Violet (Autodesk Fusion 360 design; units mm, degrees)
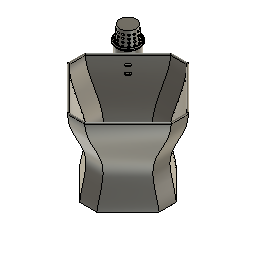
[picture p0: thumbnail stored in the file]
parameter "wall" = 1.35
parameter "height" = 119 (= "Size * 0.7") comment "Vase Hight (Medium setting)"
parameter "tolerance" = 0.15
sketch "Sketch1" plane through (0, 0, 0) normal (0, 0, 1) x axis (1, 0, 0)
  line L1 (-79.0621, -79.0621) -> (79.0621, -79.0621)
  line L2 (-79.0621, 79.0621) -> (-79.0621, -79.0621)
  line L3 (79.0621, 79.0621) -> (-79.0621, 79.0621)
  line L4 (79.0621, -79.0621) -> (79.0621, 79.0621)
  line L5 (-79.0621, 79.0621) -> (79.0621, -79.0621)
  line L6 (79.0621, 79.0621) -> (-79.0621, -79.0621)
  line L7 (-75.5266, 82.5976) -> (82.5976, -75.5266)
  line L8 (-82.5976, 75.5266) -> (75.5266, -82.5976)
  line L9 (-5.9379, 73.9379) -> (62.0621, 5.9379)
  line L10 (-73.9379, 5.9379) -> (-5.9379, 73.9379)
  line L11 (-5.9379, -62.0621) -> (-73.9379, 5.9379)
  line L12 (62.0621, 5.9379) -> (-5.9379, -62.0621)
  line L13 (-73.9379, 5.9379) -> (62.0621, 5.9379)
  line L14 (-5.9379, -62.0621) -> (-5.9379, 73.9379)
  line L15 (-5.9379, 79.0621) -> (-5.9379, 5.9379)
  line L16 (-2.4024, 9.4734) -> (-9.4734, 2.4024)
  line L17 (-60.5266, 67.5976) -> (-67.5976, 60.5266)
  circle C1 centre (-5.9379, 5.9379) radius 85
  circle C2 centre (-64.0621, 64.0621) radius 15
  circle C3 centre (-5.9379, 5.9379) radius 68
  circle C4 centre (-64.0621, 64.0621) radius 13.65
  circle C5 centre (-64.0621, 64.0621) radius 13.5
  circle C6 centre (-5.9379, 5.9379) radius 67.2
  point P6 (0, 0)
  point P1 (0, 0)
  point P7 (-5.9379, 5.9379)
  point P8 (-64.0621, 64.0621)
  point P9 (-5.9379, 5.9379)
  point P19 (-5.9379, 5.9379)
  point P15 (62.0621, 5.9379)
  point P20 (-5.9379, 5.9379)
  point P21 (-5.9379, 79.0621)
  point P22 (-9.4734, 2.4024)
  point P23 (-2.4024, 9.4734)
  point P26 (-5.9379, 5.9379)
  point P27 (-67.5976, 60.5266)
  point P28 (-60.5266, 67.5976)
  point P24 (-64.0621, 64.0621)
  horizontal L1
  perpendicular L1 L2
  parallel L1 L3
  parallel L2 L4
  coincident L5 P6
  coincident L6 P6
  coincident P1 P6
  coincident L5 P7
  coincident L5 P8
  tangent L3 C2
  tangent L4 C1
  coincident P7 P9
  perpendicular L9 L10
  parallel L9 L11
  parallel L10 L12
  coincident L13 P19
  coincident L14 P19
  coincident P9 P19
  equal L9 L12
  coincident C3 P15
  coincident P9 P20
  coincident L3 P21
  perpendicular L3 L15
  coincident L8 P22
  coincident L7 P23
  perpendicular L7 L16
  equal L2 L3
  midpoint P19 L16
  coincident P19 P26
  tangent C2 C6
  coincident L8 P27
  coincident L7 P28
  perpendicular L7 L17
  coincident P24 L17
  dimension "Size" diameter C1 = 170
  dimension "d5" diameter C2 = 30
  dimension "d8" = 5
  dimension "d9" = -5
  dimension "d16" = -17 (= "-Size * 0.1")
  dimension "d17" angle L13 L15 = 90
  dimension "d81" distance P7 P8 = 82.2 (= "Size * 0.42 + ( wall * 8 )")
work_plane "WorkPlane1" AlongDistance 39.6667 (= "height / 3")
work_plane "WorkPlane2" AlongDistance 119 (= "height")
work_plane "WorkPlane5" AlongDistance 71.4 (= "height * 0.6")
work_plane "WorkPlane4" RotateAngle 90
sketch "Sketch2" plane through (0, 0, 39.6667) normal (0, 0, 1) x axis (1, 0, 0)
  line L1 (-5.9379, 90.9379) -> (-5.9379, 5.9379)
  line L2 (-5.9379, 65.4379) -> (53.5621, 5.9379)
  line L3 (-65.4379, 5.9379) -> (-5.9379, 65.4379)
  line L4 (-5.9379, -53.5621) -> (-65.4379, 5.9379)
  line L5 (53.5621, 5.9379) -> (-5.9379, -53.5621)
  line L6 (-65.4379, 5.9379) -> (53.5621, 5.9379)
  line L7 (-5.9379, -53.5621) -> (-5.9379, 65.4379)
  circle C1 centre (-5.9379, 5.9379) radius 85
  circle C2 centre (-5.9379, 5.9379) radius 59.5
  point P2 (-5.9379, 5.9379)
  point P4 (-5.9379, 5.9379)
  point P5 (-5.9379, 90.9379)
  point P10 (-5.9379, 5.9379)
  point P6 (53.5621, 5.9379)
  coincident P2 P4
  coincident C1 P5
  vertical L1
  perpendicular L2 L3
  parallel L2 L4
  parallel L3 L5
  coincident L6 P10
  coincident L7 P10
  coincident P2 P10
  equal L2 L5
  coincident C2 P6
  dimension "d14" = -25.5 (= "-Size * 0.15")
  dimension "d15" angle L1 L6 = 90
sketch "Sketch3" plane through (0, 0, 119) normal (0, 0, 1) x axis (1, 0, 0)
  line L1 (-5.9379, 90.9379) -> (79.0621, 5.9379)
  line L2 (-90.9379, 5.9379) -> (-5.9379, 90.9379)
  line L3 (-5.9379, -79.0621) -> (-90.9379, 5.9379)
  line L4 (79.0621, 5.9379) -> (-5.9379, -79.0621)
  line L5 (-90.9379, 5.9379) -> (79.0621, 5.9379)
  line L6 (-5.9379, -79.0621) -> (-5.9379, 90.9379)
  line L7 (-5.9379, 90.9379) -> (-5.9379, 5.9379)
  circle C1 centre (-5.9379, 5.9379) radius 85
  circle C2 centre (-64.0621, 64.0621) radius 15
  circle C3 centre (-64.0621, 64.0621) radius 7.5
  point P7 (-5.9379, 5.9379)
  point P2 (-5.9379, 5.9379)
  point P3 (79.0621, 5.9379)
  point P8 (-5.9379, 5.9379)
  point P9 (-5.9379, 90.9379)
  perpendicular L1 L2
  parallel L1 L3
  parallel L2 L4
  coincident L5 P7
  coincident L6 P7
  coincident P2 P7
  equal L1 L4
  coincident C1 P3
  coincident P2 P8
  coincident C1 P9
  vertical L7
  concentric C2 C3
  dimension "d18" angle L5 L7 = 90
  dimension "d126" diameter C3 = 15
sketch "Sketch9" plane through (0, 0, 71.4) normal (0, 0, 1) x axis (1, 0, 0)
  circle C1 centre (-64.0621, 64.0621) radius 13.65
  circle C2 centre (-64.0621, 64.0621) radius 11
  concentric C1 C2
  dimension "d127" diameter C2 = 22
loft "Loft2" sketch "Sketch1" + "Sketch9" + "Sketch3" Start Weight 4.0298 Start TakeOff Angle 0 End Weight -3.9427 End TakeOff Angle 0
loft "Loft1" sketch "Sketch1" + "Sketch2" + "Sketch3" Start Weight 1.991 Start TakeOff Angle 0 End Weight -1.8239 End TakeOff Angle 0
chamfer "Chamfer4" distance 17 (= "Size * 0.1")
extrude "Extrude2" new body sketch "Sketch1" profile of C1 C2 L7 L8 C3 L9 L10 L16 C4 C5 C6 L17 blind 15 from offset 3
extrude "Extrude3" sketch "Sketch1" profile of C1 C2 L7 L8 C3 L9 L10 L16 C4 C5 C6 L17 blind -15 from offset -10
chamfer "Chamfer1" distance 1.35 (= "wall")
fillet "Fillet1" radius 3
extrude "Extrude17" sketch "Sketch1" profile of C1 L7 L8 C5 blind 20 taper -5
shell "Shell1" innerThickness 1.35 (= "wall")
extrude "Extrude18" add sketch "Sketch1" profile of C1 C2 L7 L8 C4 C5 along normal blind 20 taper -3
extrude "Extrude16" cut sketch "Sketch1" profile of C1 L7 L8 C4 C5 along normal blind 20 taper -5
offset_faces "OffsetFaces5" distance 1.35 (= "wall")
sketch "Sketch6" plane through (0, 0, 119) normal (0, 0, 1) x axis (-1, 0, 0)
  line L1 (64.0621, -47.5621) -> (64.0621, -80.5621)
  line L2 (56.3942, -49.4521) -> (71.73, -78.6721)
  line L3 (50.4829, -54.689) -> (77.6413, -73.4352)
  line L4 (47.6824, -62.0732) -> (80.4418, -66.0509)
  line L5 (48.6343, -69.9131) -> (79.4899, -58.2111)
  line L6 (53.1206, -76.4125) -> (75.0036, -51.7117)
  line L7 (60.1134, -80.0826) -> (68.0108, -48.0415)
  line L8 (68.0108, -80.0826) -> (60.1134, -48.0415)
  line L9 (75.0036, -76.4125) -> (53.1206, -51.7117)
  line L10 (79.4899, -69.9131) -> (48.6343, -58.2111)
  line L11 (80.4418, -62.0732) -> (47.6824, -66.0509)
  line L12 (77.6413, -54.689) -> (50.4829, -73.4352)
  line L13 (71.73, -49.4521) -> (56.3942, -78.6721)
  circle C1 centre (64.0621, -64.0621) radius 15.15
  circle C2 centre (64.0621, -64.0621) radius 16.5
  circle C3 centre (64.0621, -64.0621) radius 12.3
  circle C4 centre (64.0621, -64.0621) radius 15
  circle C5 centre (64.0621, -64.0621) radius 13.65
  point P5 (64.0621, -80.5621)
  point P6 (64.0621, -47.5621)
  point P3 (64.0621, -64.0621)
  coincident C2 P5
  coincident C2 P6
  vertical L1
  coincident P3 L1
  concentric C2 C4
  concentric C3 C5
  dimension "d115" distance C1 C2 = 1.35 (= "wall")
  dimension "d140" distance C1 C4 = 0.15 (= "tolerance")
  dimension "d141" distance C3 C5 = 1.35 (= "wall")
  dimension "d74" C-Pattern1-Angle = 360
extrude "Extrude7" add sketch "Sketch6" profile of C1 C2 C3 L1 L2 L3 L4 L5 L6 L7 L8 L9 L10 L11 L12 L13 no distance stored
extrude "Extrude6" add sketch "Sketch6" profile of C1 C2 L1 L2 L3 L4 L5 L6 L7 L8 L9 L10 L11 L12 L13 along normal blind 2 taper -5
extrude "Extrude8" cut sketch "Sketch6" profile of C3 L1 L2 L3 L4 L5 L6 L7 L8 L9 L10 L11 L12 L13 C5 along normal blind 2.5
rectangular_pattern "R-Pattern1" uSpaceDistance 4.5 vSpaceDistance 0
chamfer "Chamfer5" distance 0.8
circular_pattern "C-Pattern1" countU 13 TotalAngle 360
chamfer "Chamfer7" distance 2.7 (= "wall * 2") distance 1.5 (= "wall + tolerance")
sketch "Sketch7" plane through (-5.9379, 5.9379, 0) normal (0.7071, -0.7071, 0) x axis (0.7071, 0.7071, 0)
  line L1 (3.65, 6) -> (3.65, 15)
  line L2 (-3.65, 15) -> (-3.65, 6)
  line L3 (5, 15) -> (5, 6)
  line L4 (-5, 6) -> (-5, 15)
  line L5 (-3.65, 106) -> (-3.65, 97)
  line L6 (3.65, 97) -> (3.65, 106)
  line L7 (5, 106) -> (5, 97)
  line L8 (-5, 97) -> (-5, 106)
  line L9 (-2, 4.35) -> (2, 4.35)
  line L10 (2, 16.65) -> (-2, 16.65)
  line L11 (2, 3) -> (-2, 3)
  line L12 (-2, 18) -> (2, 18)
  line L13 (-2, 95.35) -> (2, 95.35)
  line L14 (2, 107.65) -> (-2, 107.65)
  line L15 (-2, 109) -> (2, 109)
  line L16 (2, 94) -> (-2, 94)
  line L17 (2, 97) -> (-2, 106)
  line L18 (2, 6) -> (-2, 15)
  line L19 (2, 104.35) -> (-2, 104.35)
  line L20 (2, 98.65) -> (-2, 98.65)
  line L21 (2, 13.35) -> (-2, 13.35)
  line L22 (2, 7.65) -> (-2, 7.65)
  arc A1 centre (-2, 6) radius 1.65 clockwise from (-2, 4.35) to (-3.65, 6)
  arc A2 centre (-2, 15) radius 1.65 clockwise from (-3.65, 15) to (-2, 16.65)
  arc A3 centre (-2, 6) radius 3 clockwise from (-2, 3) to (-5, 6)
  arc A4 centre (-2, 15) radius 3 clockwise from (-5, 15) to (-2, 18)
  arc A5 centre (2, 97) radius 1.65 clockwise from (3.65, 97) to (2, 95.35)
  arc A6 centre (2, 106) radius 1.65 clockwise from (2, 107.65) to (3.65, 106)
  arc A7 centre (2, 97) radius 3 clockwise from (5, 97) to (2, 94)
  arc A8 centre (2, 106) radius 3 clockwise from (2, 109) to (5, 106)
  arc A9 centre (2, 6) radius 1.65 clockwise from (3.65, 6) to (2, 4.35)
  arc A10 centre (2, 15) radius 1.65 clockwise from (2, 16.65) to (3.65, 15)
  arc A11 centre (2, 6) radius 3 clockwise from (5, 6) to (2, 3)
  arc A12 centre (2, 15) radius 3 clockwise from (2, 18) to (5, 15)
  arc A13 centre (-2, 97) radius 1.65 clockwise from (-2, 95.35) to (-3.65, 97)
  arc A14 centre (-2, 106) radius 1.65 clockwise from (-3.65, 106) to (-2, 107.65)
  arc A15 centre (-2, 106) radius 3 clockwise from (-5, 106) to (-2, 109)
  arc A16 centre (-2, 97) radius 3 clockwise from (-2, 94) to (-5, 97)
  circle C1 centre (2, 106) radius 1.65
  circle C2 centre (-2, 106) radius 1.65
  circle C3 centre (-2, 97) radius 1.65
  circle C4 centre (2, 97) radius 1.65
  circle C5 centre (0, 101.5) radius 1.65
  circle C6 centre (2, 15) radius 1.65
  circle C7 centre (-2, 15) radius 1.65
  circle C8 centre (-2, 6) radius 1.65
  circle C9 centre (2, 6) radius 1.65
  circle C10 centre (0, 10.5) radius 1.65
  point P39 (-2, 106)
  point P42 (-2, 106)
  point P20 (2, 97)
  point P43 (2, 97)
  point P19 (-2, 15)
  point P44 (-2, 15)
  point P27 (2, 6)
  point P45 (2, 6)
  point P49 (2, 97)
  point P50 (0, 101.5)
  point P52 (-2, 15)
  point P54 (2, 6)
  point P55 (0, 10.5)
  point P56 (-2, 104.35)
  point P57 (2, 104.35)
  point P58 (-2, 98.65)
  point P59 (2, 98.65)
  point P60 (-2, 13.35)
  point P61 (2, 13.35)
  point P62 (-2, 7.65)
  point P63 (2, 7.65)
  point P11 (2, 107.65)
  point P18 (-2, 6)
  point P53 (-2, 6)
  coincident P39 P42
  coincident P20 P43
  coincident P19 P44
  coincident P27 P45
  concentric A6 C1
  concentric A14 C2
  concentric A13 C3
  coincident P43 P49
  midpoint L17 P50
  concentric A10 C6
  coincident P44 P52
  coincident P45 P54
  midpoint L18 P55
  equal C1 C2
  equal C1 C5
  equal C1 C4
  equal C1 C3
  equal C1 C6
  equal C1 C7
  equal C1 C10
  equal C1 C9
  equal C1 C8
  coincident C2 P56
  coincident C1 P57
  tangent C1 L19
  horizontal L19
  coincident C3 P58
  coincident C4 P59
  tangent C4 L20
  parallel L19 L20
  coincident C7 P60
  coincident C6 P61
  tangent C6 L21
  parallel L20 L21
  coincident C8 P62
  coincident C9 P63
  tangent C9 L22
  parallel L21 L22
  coincident P11 C1
  coincident P18 P53
extrude "Extrude19" cut sketch "Sketch7" profile of L1 L2 L5 L6 A1 A2 A5 A6 A9 L9 L10 A10 L13 A13 A14 L14 C1 C2 C3 C4 C5 C6 C7 C8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 against normal blind 82.2 (magnitude of "-d81")
extrude "Extrude14" cut sketch "Sketch7" profile of A1 A2 A5 A6 A9 L9 L10 A10 L13 A13 A14 L14 C1 C2 C3 C4 C6 C7 C8 C9 L19 L20 L21 L22 against normal blind 85 (magnitude of "-Size / 2")
combine "Combine6"
remove_body "RemoveBody21"
remove_body "RemoveBody22"
combine "Combine7"
remove_body "RemoveBody25"
remove_body "RemoveBody27"
sketch "Sketch8" plane through (0, 0, 0) normal (0.7071, 0.7071, 0) x axis (-0.7071, 0.7071, 0)
  line L1 (103.504, 98.4562) -> (78.2595, 94.005)
  line L2 (43.0145, 66.35) -> (-78.5796, 66.35)
  line L3 (103.504, 98.4562) -> (103.504, 99.8271)
  line L4 (103.504, 99.8271) -> (78.1133, 95.35)
  curve K1 (103.9958, 20) -> (104.2182, 114.9501)
  curve K2 (78.1133, 95.35) -> (77.1991, 20)
  curve K3 (76.9768, 114.9501) -> (77.1922, 107.65)
  point P6 (103.504, 99.8271)
  point P5 (78.1133, 95.35)
  point P10 (78.1133, 95.35)
  point P13 (78.2595, 94.005)
  point P2 (-78.5796, 66.35)
  horizontal L2
  parallel L1 L4
  vertical L3
  coincident P6 K1
  coincident P5 P10
  coincident K2 P13
  coincident P2 L1
  dimension "d84" angle L1 L2 = 10
  dimension "d136" distance L1 L4 = 1.35 (= "wall")
extrude "Extrude11" new body sketch "Sketch8" profile of L1 L3 L4 distance 20
combine "Combine5"
remove_body "RemoveBody9"
remove_body "RemoveBody14"
work_plane "WorkPlane3" RotateAngle 90
sketch "Sketch5" plane through (-5.9379, 30, 100) normal (1, 0, 0) x axis (0, 1, 0)
  line L1 (47.5671, 19) -> (48.9171, 19)
  line L2 (48.2421, 18.2) -> (48.2421, 19)
  line L3 (-12.6005, 19) -> (47.5671, 19)
  line L4 (60.9379, 19) -> (-24.0621, 19)
  circle C1 centre (48.2421, 18.2) radius 1.25
  point P2 (48.9171, 19)
  point P3 (47.5671, 19)
  point P5 (48.2421, 19)
  point P4 (48.2421, 18.2)
  point P6 (48.2421, 18.2)
  point P7 (47.5671, 19)
  coincident P2 L4
  coincident P3 L3
  midpoint L1 P5
  perpendicular L1 L2
  coincident P4 P6
  coincident P3 P7
  dimension "d36" diameter C1 = 2.5
  dimension "d135" distance P5 P6 = 0.8
sweep "Sweep1" sketch "Sketch5" TwistAngle 0 TaperAngle 0
combine "Combine8"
